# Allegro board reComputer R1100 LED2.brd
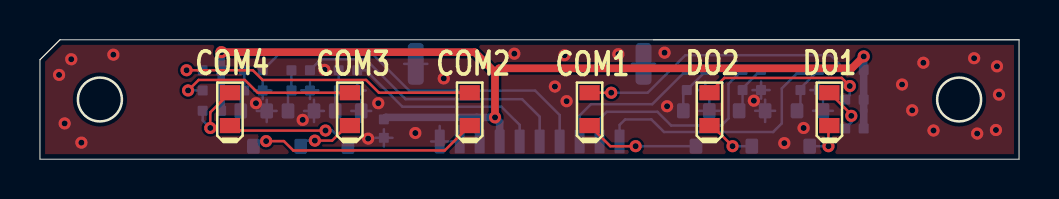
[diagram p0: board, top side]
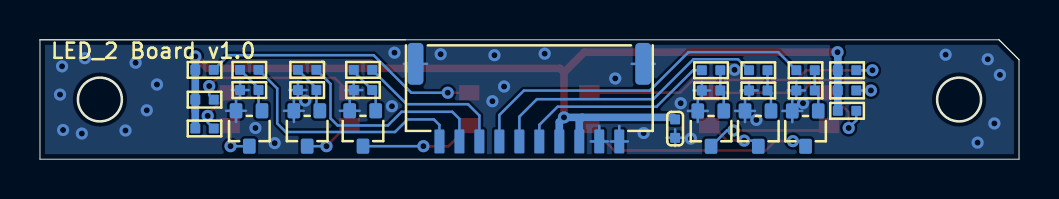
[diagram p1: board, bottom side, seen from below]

Outline 49 x 6 mm; copper layers: TOP, BOTTOM. Coordinates in mm from the lower left corner of the outline.
Outline path: circle c3,3 r1.1 ; circle c3,3 r1.1 ; circle c46,3 r1.1 ; circle c46,3 r1.1 ; 0,5 0,0 49,0 49,6 ; 0,5 1,6 ; 0,5 1,6 ; 1,6 49,6 ; 49,6 30.7,6

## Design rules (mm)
constraint set DEFAULT: min track width 0.127

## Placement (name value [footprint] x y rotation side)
J1  1.0-10A-WT  [JST10_2P_1D0_12_35X4_3X3_2MM]  24.51 0.89 0 bottom
LC3  1uF  [C0402]  17.21 1.54 90 bottom
LED1  Emerald Green  [LED0603]  39.51 2.51 90 top
LED4  Emerald Green  [LED0603]  33.51 2.51 90 top
LED5  Emerald Green  [LED0603]  21.51 2.51 90 top
LED6  Emerald Green  [LED0603]  15.51 2.51 90 top
LED7  Emerald Green  [LED0603]  9.51 2.51 90 top
LED8  Emerald Green  [LED0603]  27.51 2.51 90 top
LQ2  BSS138W  [SOT-323-3]  13.05 1.54 0 bottom
LQ3  BSS138W  [SOT-323-3]  15.41 1.54 0 bottom
LQ4  BSS138W  [SOT-323-3]  10.68 1.54 0 bottom
LQ5  BSS138W  [SOT-323-3]  32.83 1.54 0 bottom
LQ6  BSS138W  [SOT-323-3]  38.52 1.54 0 bottom
LQ7  BSS138W  [SOT-323-3]  35.63 1.54 0 bottom
LR2  51R  [R0402]  8.61 4.47 180 bottom
LR5  51R  [R0402]  40.76 1.54 180 bottom
LR6  51R  [R0402]  40.76 2.99 180 bottom
LR7  51R  [R0402]  8.61 3.45 180 bottom
LR8  1K  [R0402]  13.05 4.47 180 bottom
LR9  100K  [R0402]  13.05 3.45 0 bottom
LR10  51R  [R0402]  8.61 2.43 180 bottom
LR11  1K  [R0402]  15.41 4.47 180 bottom
LR12  100K  [R0402]  15.41 3.45 0 bottom
LR15  1K  [R0402]  10.68 4.47 180 bottom
LR16  100K  [R0402]  10.68 3.45 0 bottom
LR17  51R  [R0402]  40.76 4.49 180 bottom
LR18  1K  [R0402]  32.83 4.49 0 bottom
LR19  100K  [R0402]  32.83 3.47 0 bottom
LR20  1K  [R0402]  38.52 4.49 0 bottom
LR21  100K  [R0402]  38.52 3.47 0 bottom
LR22  1K  [R0402]  35.63 4.49 0 bottom
LR23  100K  [R0402]  35.63 3.47 0 bottom

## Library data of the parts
J1 = JST_10+2P
LC3 = CC
LED1 LED4-LED8 = Single LED
LQ2-LQ7 = NMOS_123
LR2 LR5-LR12 LR15-LR23 = R

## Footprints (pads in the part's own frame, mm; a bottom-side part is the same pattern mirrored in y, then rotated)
C0402
  rrect 0.5x0.5 smd: 1(-0.463,0) 2(0.463,0)
JST10_2P_1D0_12_35X4_3X3_2MM
  rrect 0.5x1.2 smd: 1(-4.5,0) 2(-3.5,0) 3(-2.5,0) 4(-1.5,0) 5(-0.5,0) 6(0.5,0) 7(1.5,0) 8(2.5,0) 9(3.5,0) 10(4.5,0)
  rrect 0.8x2.1 smd: S1(-5.7,-3.9) S2(5.7,-3.9)
LED0603
  rect 0.762x1.016 smd: 1(0.826,0) 2(-0.826,0)
R0402
  rrect 0.5x0.5 smd: 1(-0.463,0) 2(0.463,0)
SOT-323-3
  rrect 0.635x0.762 smd: 1(-0.635,-0.889) 2(0.665,-0.889) 3(0,0.889)

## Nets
GND: J1.1 J1.2 J1.S1 J1.S2 LC3.1 LQ2.2(S) LQ3.2(S) LQ4.2(S) LQ5.2(S) LQ6.2(S) LQ7.2(S) LR9.2 LR12.2 LR16.2 LR19.2 LR21.2 LR23.2
VDD_3V3_SYS: J1.3 J1.4 LC3.2 LR2.1 LR5.1 LR6.1 LR7.1 LR10.1 LR17.1
CM4_OUT1_LED: J1.10 LR20.1
CM4_OUT2_LED: J1.9 LR22.1
RS232_LED1: J1.6 LR8.1
RS232_LED2: J1.5 LR11.1
RS485_LED1: J1.8 LR18.1
RS485_LED2: J1.7 LR15.1
N19189: LED4.1 LR6.2
N20057: LED6.2(C) LQ2.3
N20113: LQ2.1 LR8.2 LR9.1
N20605: LED7.2(C) LQ3.3
N20661: LQ3.1 LR11.2 LR12.1
N36522: LQ4.1 LR15.2 LR16.1
N36850: LED8.2(C) LQ5.3
N36906: LQ5.1 LR18.2 LR19.1
N37720: LED1.1 LR5.2
N48529: LQ6.1 LR20.2 LR21.1
N48764: LQ7.1 LR22.2 LR23.1
N49368: LED1.2(C) LQ6.3
N49372: LED4.2(C) LQ7.3
N330391: LED5.1 LR2.2
N331441: LED6.1 LR7.2
N332491: LED7.1 LR10.2
N339140: LED5.2(C) LQ4.3
N368181: LED8.1 LR17.2

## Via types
v1: diameter 0.61, hole 0.305, TOP to BOTTOM, 46 vias

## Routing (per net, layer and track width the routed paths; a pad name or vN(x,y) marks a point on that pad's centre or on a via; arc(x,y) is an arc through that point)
GND: length 29.7
  BOTTOM w0.127: 15.58,2.43 LQ3.2 ; LQ3.2 16.08,1.87 ; LQ3.2 16.57,2.43 ; LQ3.2 16.08,2.99 ; LR19.2 33.72,3.47 ; LR19.2 33.3,3.05 ; LR19.2 33.3,3.9 ; LR19.2 32.87,3.47 ; 36.29,1.87 LQ7.2 ; LQ7.2 36.29,2.99 ; LQ7.2 35.8,2.43 ; LQ7.2 36.79,2.43 ; 38.98,3.05 LR21.2 ; LR21.2 38.98,3.9 ; LR21.2 38.56,3.47 ; LR21.2 39.41,3.47 ; 38.69,2.43 LQ6.2 ; LQ6.2 39.19,2.99 ; LQ6.2 39.19,1.87 ; LQ6.2 39.68,2.43 ; LC3.1 17.21,1.5 ; LC3.1 16.78,1.07 ; LC3.1 17.64,1.07 ; LC3.1 17.21,0.65 ; 30.79,4.79 J1.S2 29.63,4.79 ; 36.09,3.05 LR23.2 ; LR23.2 36.52,3.47 ; LR23.2 36.09,3.9 ; LR23.2 35.66,3.47 ; 19.39,4.79 J1.S1 18.23,4.79 ; LQ5.2 33.5,2.99 ; LQ5.2 33.99,2.43 ; LQ5.2 33,2.43 ; LR16.2 11.15,3.88 ; LR16.2 11.57,3.45 ; LR16.2 11.15,3.03 ; LR16.2 10.72,3.45 ; 13.08,3.45 LR9.2 ; LR9.2 13.51,3.88 ; LR9.2 13.94,3.45 ; LR9.2 13.51,3.03 ; J1.2 21.01,1.67 ; J1.2 20.58,0.89 ; J1.2 21.44,0.89 ; 15.45,3.45 LR12.2 ; LR12.2 15.88,3.03 ; LR12.2 15.88,3.88 ; LR12.2 16.3,3.45 ; LQ4.2 11.35,2.99 ; LQ4.2 10.85,2.43 ; LQ4.2 11.84,2.43 ; LQ4.2 11.35,1.87 ; 34.87,4.93 34.87,4.93 ; 13.71,1.87 LQ2.2 ; LQ2.2 14.21,2.43 ; LQ2.2 13.22,2.43 ; LQ2.2 13.71,2.99 ; 19.58,0.89 J1.1 ; J1.1 20.01,1.67 ; J1.1 20.44,0.89 ; 34.72,4.78 34.72,4.79
  vias: v1(0.96,4.24) v1(1.23,1.8) v1(1.57,5.02) v1(2.07,0.83) v1(3.67,5.25) v1(10.81,2.81) v1(13.15,1.98) v1(14.24,4.49) v1(16.42,1.04) v1(16.93,2.81) v1(18.79,1.31) v1(20.21,4.06) v1(23.74,5.3) v1(25.77,3.65) v1(26.25,5.23) v1(26.36,2.91) v1(28.95,5.28) v1(31.26,5.35) v1(31.38,2.66) v1(35.73,2.94) v1(37.25,0.81) v1(38.22,1.57) v1(43.14,3.75) v1(43.65,2.46) v1(44.21,4.85) v1(44.72,1.44) v1(46.75,5.07) v1(46.9,1.29) v1(47.84,1.47) v1(47.89,4.67) v1(48,3.25)
VDD_3V3_SYS: length 49.9
  TOP w0.381: 22.77,4.36 v1(22.77,2.1) ; 22.77,4.36 22.98,4.57 40.63,4.57 v1(41.23,5.16) ; 22.77,4.36 21.76,5.38 v1(9.08,5.38)
  BOTTOM w0.381: J1.4 23.01,1.87 v1(22.77,2.1) 21.86,2.1 ; 21.86,2.1 22.01,1.95 J1.3 ; 21.86,2.1 17.31,2.1 LC3.2 ; LR10.1 LR7.1 LR2.1 9.07,5.36 v1(9.08,5.38) ; LR5.1 41.23,1.55 41.23,2.44 41.23,2.44 LR6.1 LR17.1 v1(41.23,5.16)
CM4_OUT1_LED: length 12.6
  BOTTOM w0.127: LR20.1 37.13,3.56 37.13,1.8 36.69,1.37 31.23,1.37 30.6,2 29.29,2 29.01,1.72 J1.10
CM4_OUT2_LED: length 10.9
  BOTTOM w0.127: LR22.1 34.46,3.78 34.46,2.05 34.1,1.7 31.59,1.7 30.9,2.38 28.36,2.38 28.01,2.03 J1.9
RS232_LED1: length 14.2
  BOTTOM w0.127: J1.6 25.01,2.14 24.13,3.02 18.3,3.02 16.29,5.02 14.06,5.02 LR8.1
RS232_LED2: length 10.1
  BOTTOM w0.127: LR11.1 16.31,4.47 18.14,2.64 23.09,2.64 24.01,1.72 J1.5
RS485_LED1: length 7.6
  BOTTOM w0.127: J1.8 27.01,2.2 27.57,2.76 30.64,2.76 LR18.1
RS485_LED2: length 17.9
  BOTTOM w0.127: J1.7 26.01,2.22 24.78,3.45 18.48,3.45 16.55,5.38 12.05,5.38 LR15.1
N19189: length 8.3
  TOP w0.127: v1(40.53,3.68) 40.12,4.08 34.25,4.08 LED4.1
  BOTTOM w0.127: v1(40.53,3.68) 40.53,3.22 LR6.2
N20057: length 2.9
  TOP w0.127: v1(13.76,0.93) 14.62,0.93 15.38,1.69 LED6.2
  BOTTOM w0.127: LQ2.3 13.33,0.93 v1(13.76,0.93)
N20113: length 2.1
  BOTTOM w0.127: LQ2.1 12.41,3.28 LR9.1 LR8.2
N20605: length 6.3
  TOP w0.127: v1(14.29,1.44) 9.75,1.44 LED7.2
  BOTTOM w0.127: v1(14.29,1.44) 14.62,1.44 LQ3.3
N20661: length 2.1
  BOTTOM w0.127: LR11.2 LR12.1 14.78,3.28 LQ3.1
N36522: length 2.1
  BOTTOM w0.127: LR15.2 LR16.1 10.05,3.28 LQ4.1
N36850: length 5.8
  TOP w0.127: v1(29.81,0.65) 28.54,0.65 LED8.2
  BOTTOM w0.127: LQ5.3 v1(29.81,0.65)
N36906: length 2.5
  BOTTOM w0.127: LQ5.1 32.2,3.3 LR19.1 33.3,4.4 LR18.2
N37720: length 2.6
  TOP w0.127: v1(40.6,2.18) 40.6,2.24 LED1.1 39.38,3.46
  BOTTOM w0.127: LR5.2 40.6,1.85 v1(40.6,2.18)
N48529: length 2.5
  BOTTOM w0.127: LR20.2 38.06,3.56 LR21.1 38.06,2.6 LQ6.1
N48764: length 2.5
  BOTTOM w0.127: LR22.2 35.16,3.56 LR23.1 35.16,2.6 LQ7.1
N49368: length 2
  TOP w0.127: LED1.2 39.46,1.64 v1(39.46,0.65)
  BOTTOM w0.127: LQ6.3 v1(39.46,0.65)
N49372: length 2.5
  TOP w0.127: LED4.2 33.63,1.69 v1(34.66,0.65)
  BOTTOM w0.127: LQ7.3 v1(34.66,0.65)
N330391: length 15.4
  TOP w0.127: LED5.1 16.96,3.34 16.32,3.98 11.14,3.98 10.65,4.47 v1(7.34,4.47)
  BOTTOM w0.127: LR2.2 v1(7.34,4.47)
N331441: length 9.3
  TOP w0.127: LED6.1 10.89,3.34 10.25,3.98 7.94,3.98 v1(7.41,3.45)
  BOTTOM w0.127: LR7.2 v1(7.41,3.45)
N332491: length 3.2
  TOP w0.127: LED7.1 8.52,2.36 v1(8.52,1.57)
  BOTTOM w0.127: v1(8.52,1.57) 8.14,1.95 LR10.2
N339140: length 11.6
  TOP w0.127: LED5.2 20.26,0.44 12.68,0.44 12.21,0.91 v1(11.32,0.91)
  BOTTOM w0.127: LQ4.3 10.94,0.91 v1(11.32,0.91)
N368181: length 13.9
  TOP w0.127: v1(28.59,3.34) LED8.1
  BOTTOM w0.127: v1(28.59,3.34) 30.41,3.34 32.3,5.23 39.56,5.23 LR17.2

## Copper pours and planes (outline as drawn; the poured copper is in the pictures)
GND on TOP: 1.11,5.75 48.75,5.75 48.75,0.25 0.25,0.25 0.25,4.89 ; 2 cut-outs
GND on BOTTOM: 1.11,5.75 48.75,5.75 48.75,0.25 0.25,0.25 0.25,4.89 ; 11 cut-outs

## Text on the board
Ref Des/Silkscreen Bottom: LED_2 Board v1.0
Ref Des/Silkscreen Top: COM4 | COM3 | COM2 | COM1 | DO2 | DO1
User.22: FIGURE | FINISHED_SIZE | 12.0 | DRILL CHART: TOP to BOTTOM | ALL UNITS ARE IN MILS | PLATED | QTY | 46 | TOTAL HOLES:
